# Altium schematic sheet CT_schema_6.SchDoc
size 278 x 170 mm
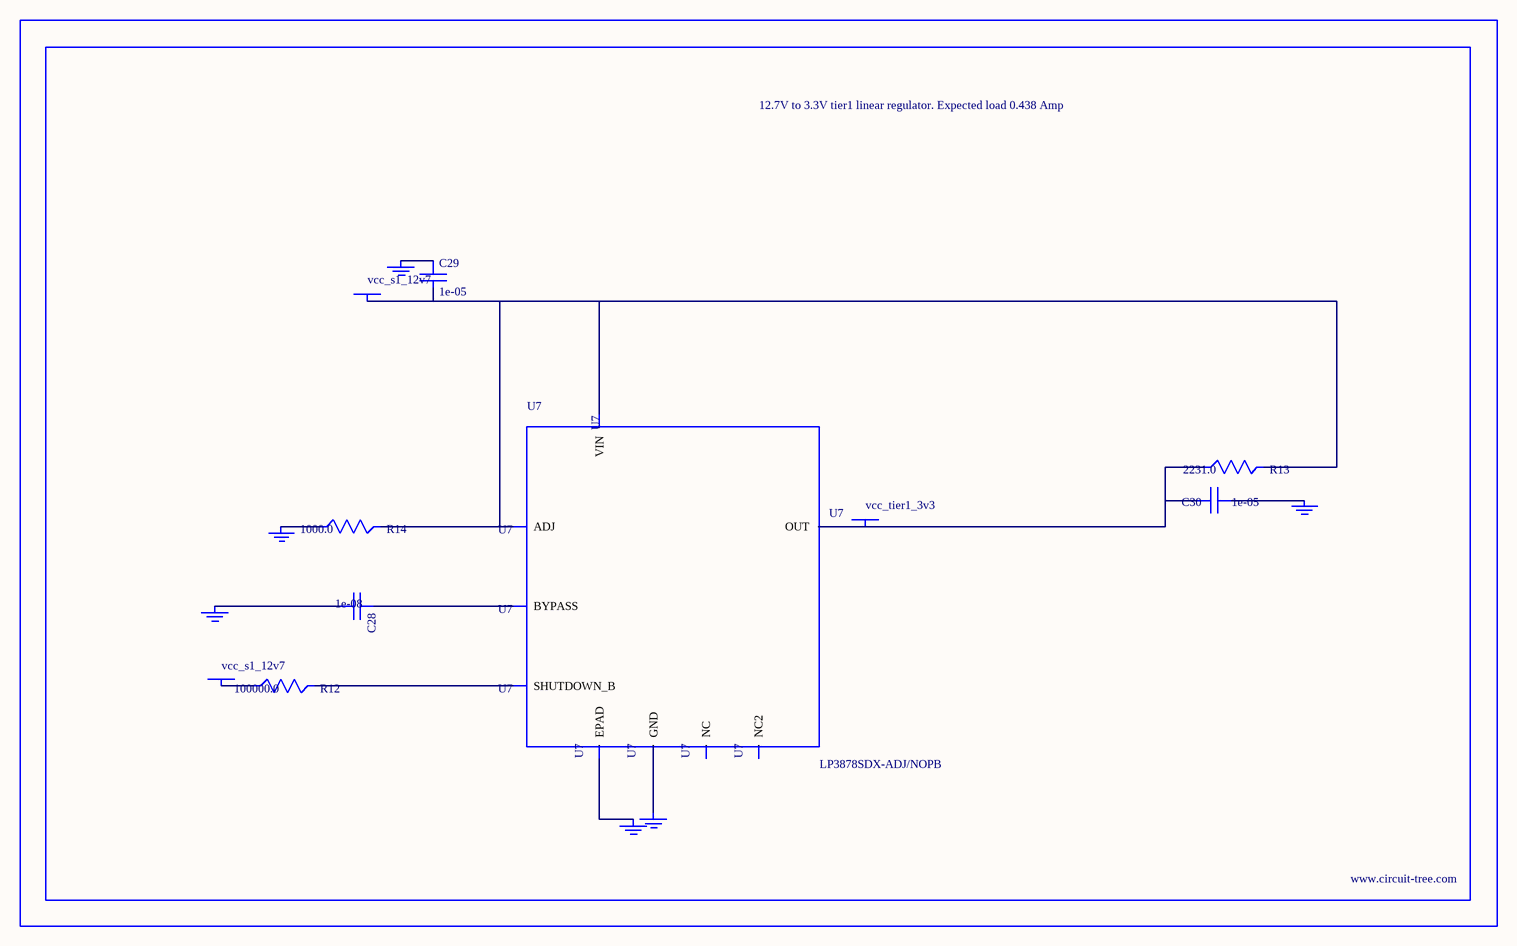
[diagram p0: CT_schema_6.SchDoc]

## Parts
BORDER5  (no value)
C28  1e-08  [C0402]
C29  1e-05  [C1210]
C30  1e-05  [C1210]
GND_INSTANCE_5_0  (no value)
GND_INSTANCE_5_1  (no value)
GND_INSTANCE_5_2  (no value)
GND_INSTANCE_5_3  (no value)
GND_INSTANCE_5_4  (no value)
GND_INSTANCE_5_5  (no value)
POWER_INSTANCE_5_0  vcc_s1_12v7
POWER_INSTANCE_5_1  vcc_s1_12v7
POWER_INSTANCE_5_2  vcc_tier1_3v3
R12  100000.0  [R0603]
R13  2231.0  [R0603]
R14  1000.0  [R0603]
U7  LP3878SDX-ADJ/NOPB  [WSON-8]

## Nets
NetC28_1: C28.1 U7.1(BYPASS)
NetC28_2: C28.2 GND_INSTANCE_5_0.0(GND)
NetC29_1: C29.1 GND_INSTANCE_5_1.0(GND)
NetC29_2: C29.2 POWER_INSTANCE_5_0.0(PWR) R13.2 R14.2 U7.4(VIN) U7.6(ADJ)
NetC30_1: C30.1 GND_INSTANCE_5_2.0(GND)
NetC30_2: C30.2 POWER_INSTANCE_5_2.0(PWR) R13.1 U7.5(OUT)
NetGND_INSTANCE_5_3_0: GND_INSTANCE_5_3.0(GND) R14.1
NetGND_INSTANCE_5_4_0: GND_INSTANCE_5_4.0(GND) U7.PAD(EPAD)
NetGND_INSTANCE_5_5_0: GND_INSTANCE_5_5.0(GND) U7.3(GND)
NetPOWER_INSTANCE_5_1_0: POWER_INSTANCE_5_1.0(PWR) R12.1
NetR12_2: R12.2 U7.8(SHUTDOWN_B)

Not connected (* = marked no-connect by the designer): U7 2(NC) 7(NC2)

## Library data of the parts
BORDER5 = BORDER_PAGE5
C28 = C0402C103K3RAC
C29 = C1210C106K5PACTU
C30 = GRM32DR61E106MA12L
GND_INSTANCE_5_0-GND_INSTANCE_5_5 = GND
POWER_INSTANCE_5_0-POWER_INSTANCE_5_2 = PWR
R12 = RC0603JR-07100KL
R13 = R13
R14 = RC0603JR-071KL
